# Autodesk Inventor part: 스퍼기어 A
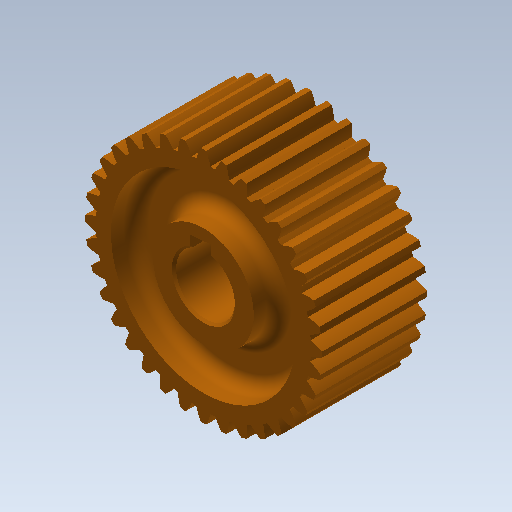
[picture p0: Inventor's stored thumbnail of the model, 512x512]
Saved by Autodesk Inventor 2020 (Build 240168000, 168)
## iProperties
Created: 2020-04
Part Number: 스퍼기어 A
Material: 강철, 연강
Document SubType Name: Modeling
Designer: mduedu
Categories: <?xml version="1.0" encoding="UTF-16"?> <MemberInstance><Categories><FamilyTemplate><FamilyTemplateParameter ValueType="xs:double" Id="1" ObjectReferenceKey="da
Density: 7.86 g/cm^3
Mass: 321.469 g
Surface Area: 147.737 cm^2
Volume: 40.8993 cm^3
Appearance: 주황색
Author: mduedu
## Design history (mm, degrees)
sketch "Sketch1"
  geometry: C1 r 28.2 at (0, 0)
  constraints: 1 centre point
  dimensions: "d0" = 56.4 diameter of C1 (= da_da)
extrude "Extrusion1" new body sketch "Sketch1" distance "d1" = 25 (= da_b); taper "d2" = 0 deg
workplane "Work Plane2"
sketch "Sketch2"
  geometry: C1 r 28.2 at (0, 0) reference; C2 r 27 at (0, 0)
  constraints: 1 centre point, 1 coincident
  dimensions: "d3" = 54 diameter of C2 (= da_dw)
feature "피치 지름" sketch "Sketch2" dims "d4" = 10, "d5" = 0
workplane "Work Plane8"
workplane "Work Plane9"
feature "스퍼 기어" dims "da_b" = 25, "da_d" = 54, "da_aw" = 45, "da_da" = 56.4, "da_df" = 51.129, "da_dw" = 54, angle "da_beta" = 0 deg, "da_lefttooth" = 0, "da_righttooth" = 0
node "작업 평면11"
sketch "스케치3"
  geometry: C1 r 12 at (0, 0); C2 r 22 at (0, 0); 1 further point
  constraints: 2 centre point, 2 coincident
  dimensions: "d49" = 24 diameter of C1; "d50" = 44 diameter of C2
extrude "돌출2" cut sketch "스케치3" distance "d51" = 6; taper "d52" = 0 deg
fillet "모깎기1" dims "d53" = 3
sketch "스케치4"
  geometry: L1 (-3.06, 6.296)-(1.921, 6.731); L2 (1.921, 6.731)-(1.68, 9.483); L3 (1.68, 9.483)-(-3.301, 9.047); L4 (-3.301, 9.047)-(-3.06, 6.296); L5 (-3.728, 42.608)-(3.728, -42.608) reference; A1 r 7 centre (0, 0) between (-3.06, 6.296) and (1.921, 6.731); 1 further point
  constraints: 8 end point, 4 perpendicular, 2 point on circle, 1 centre point, 1 coincident
  dimensions: "d54" = 14 diameter of A1; "d63" = 16.3 dimension on A1 L3; "d64" = 5 distance of L2.end L3.end
extrude "돌출3" cut sketch "스케치4" extent not by distance; stored distance "d58" = 6; taper "d59" = 0 deg
chamfer "모따기1" distance "d60" = 0.5; stored, may be unused: second distance "d61" = 2, angle "d62" = 45 deg
body "Solid1"
mirror "대칭1"
body "Srf1"
other parameters: "d16" = 45 (= da_aw), "d17" = 0, "d34" = 5 deg (computed from da_z), "d39" = 0, "d41" = 0, "d43" = 45 (= da_aw), "d46" = 45 (= da_aw), "d47" = 0, "d48" = 0
